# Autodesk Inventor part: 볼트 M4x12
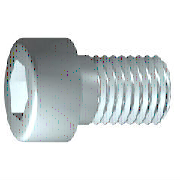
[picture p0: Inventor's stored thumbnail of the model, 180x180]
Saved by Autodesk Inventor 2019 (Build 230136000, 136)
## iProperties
IsCustomPart: 0
Created: 2012-02
Part Number: 볼트 M4x12
Material: 강철, 연강
Description: 6각머리 태핑 나사
Document SubType Name: Modeling
Standard: KS B 1003
Designer: mduedu
Standards Organization: KS
Language: ko-KR
Size Designation: M 4 x 12
Categories: <MemberInstance><Categories><Category DisplayName="조임쇠" InternalName="e4da775c-781d-43d5-af7c-5136215cf5a6" Mnemonic="FSTN"><Category DisplayName="볼트" InternalN
Density: 1 g/cm^3
Appearance: 강철
Author: mduedu
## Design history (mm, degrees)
sketch "스케치1"
  geometry: L1 (-1, 0)-(12, 0); L2 (12, 0)-(12, 2); L3 (12, 2)-(1.75, 2); L4 (1.75, 2)-(1.32, 2); L5 (1.32, 2)-(0, 2); L6 (0, 2)-(0, 3.5); L7 (0, 3.5)-(-4, 3.5); L8 (-4, 3.5)-(-4, 1.732); L9 (-4, 1.732)-(-2, 1.732); L10 (-2, 1.732)-(-1, 0); L11 (-7.2, 0)-(15.2, 0) reference; L12 (0, -0.7)-(0, 4.2) reference; L13 (1.75, 2)-(0, 2)
  constraints: 22 end point, 6 parallel, 2 collinear, 2 perpendicular, 1 horizontal, 1 point on line
  dimensions: "d1" = 10.25 distance from line of L3.end L2 (= GEL); "d2" = 0.42952 distance of L4.end L3.end (computed from GAL); "d3" = 4 distance between parallel lines of L8 L6 (= KOH); "d4" = 2 distance of L8.end L9.end (= INTI); "d5" = 60 deg angle of L10 L1; "d6" = 4 diameter of L3 L1 (= GD); "d7" = 4 diameter of L5 L1 (= BDM); "d8" = 3.4641 diameter of L9 L1 (= 1.1547 x SW); "d9" = 7 diameter of L7 L1 (= KOD); "d26" = 12 distance between parallel lines of L12 L2 (= NLG)
revolve "본체" sketch "스케치1" stored, may be unused: angle "d10" = 90 deg
sketch "스케치2"
  geometry: L1 (0, -4.9)-(0, 4.9) reference; L2 (-4.9, 0)-(4.9, 0) reference; L3 (1.732, 0)-(0.866, -1.5); L4 (0.866, -1.5)-(-0.866, -1.5); L5 (-0.866, -1.5)-(-1.732, 0); L6 (-1.732, 0)-(-0.866, 1.5); L7 (-0.866, 1.5)-(0.866, 1.5); L8 (0.866, 1.5)-(1.732, 0); 2 further points
  constraints: 12 end point, 1 coincident, 1 horizontal alignment, 1 point on line, 12 other
extrude "슬롯" join sketch "스케치2" stored distance "d11" = 10; taper "d12" = 0 deg
workplane "Work Plane1"
fillet "Fillet2" dims "d30" = 0.1 (= R)
body "Solid1"
fillet "모깎기1" dims "d17" = 0.4 (= RR)
feature "스레드" dims "d13" = 10.25 (= GEL), "d14" = 0
chamfer "모따기1" distance "d15" = 0.42941 (= -0.5 x SPD + 0.5 x GD); stored, may be unused: second distance "d16" = 0.42941 (= GUL), angle "d27" = 45 deg
other parameters: "GD" = 4 (= NND) [user parameter; used in 2 equation terms], "NLG" = 12 [user parameter; used in 1 equation term], "GEL" = 10.25 [user parameter; used in 2 equation terms], "KOD" = 7 [user parameter; used in 1 equation term], "KOH" = 4 [user parameter; used in 1 equation term], "INTI" = 2 [user parameter; used in 1 equation term], "GAL" = 0.42941 (= 0.61345 x PTC) [user parameter; used in 1 equation term], "GUL" = 0.42941 (= 0.61345 x PTC) [user parameter; used in 1 equation term], "BDM" = 4 (= NND) [user parameter; used in 1 equation term], "SW" = 3 [user parameter; used in 2 equation terms], "RR" = 0.4 [user parameter; used in 1 equation term], "SPD" = 3.14117 (= NND - 1.2269 x PTC) [user parameter; used in 1 equation term], "d19" = 0, "d28" = 0, "d29" = 0, "R" = 0.1 [user parameter; used in 1 equation term], "PHH" = 0.2 [user parameter], "GD1" = 3.14117 (= THREADDIA - 1.2269 x PTC) [user parameter], "THREADDIA" = 4 [user parameter; used in 1 equation term], "FAWI" = 45 deg [user parameter], "TPU" = 14.28571 (computed from PTC) [user parameter], "PTC" = 0.7 [user parameter; used in 5 equation terms], "NND" = 4 [user parameter; used in 3 equation terms], "TOA" = 30 deg [user parameter], "E0" = 3.465 (= 1.155 x SW) [user parameter]
